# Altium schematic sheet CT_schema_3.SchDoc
size 283 x 174 mm
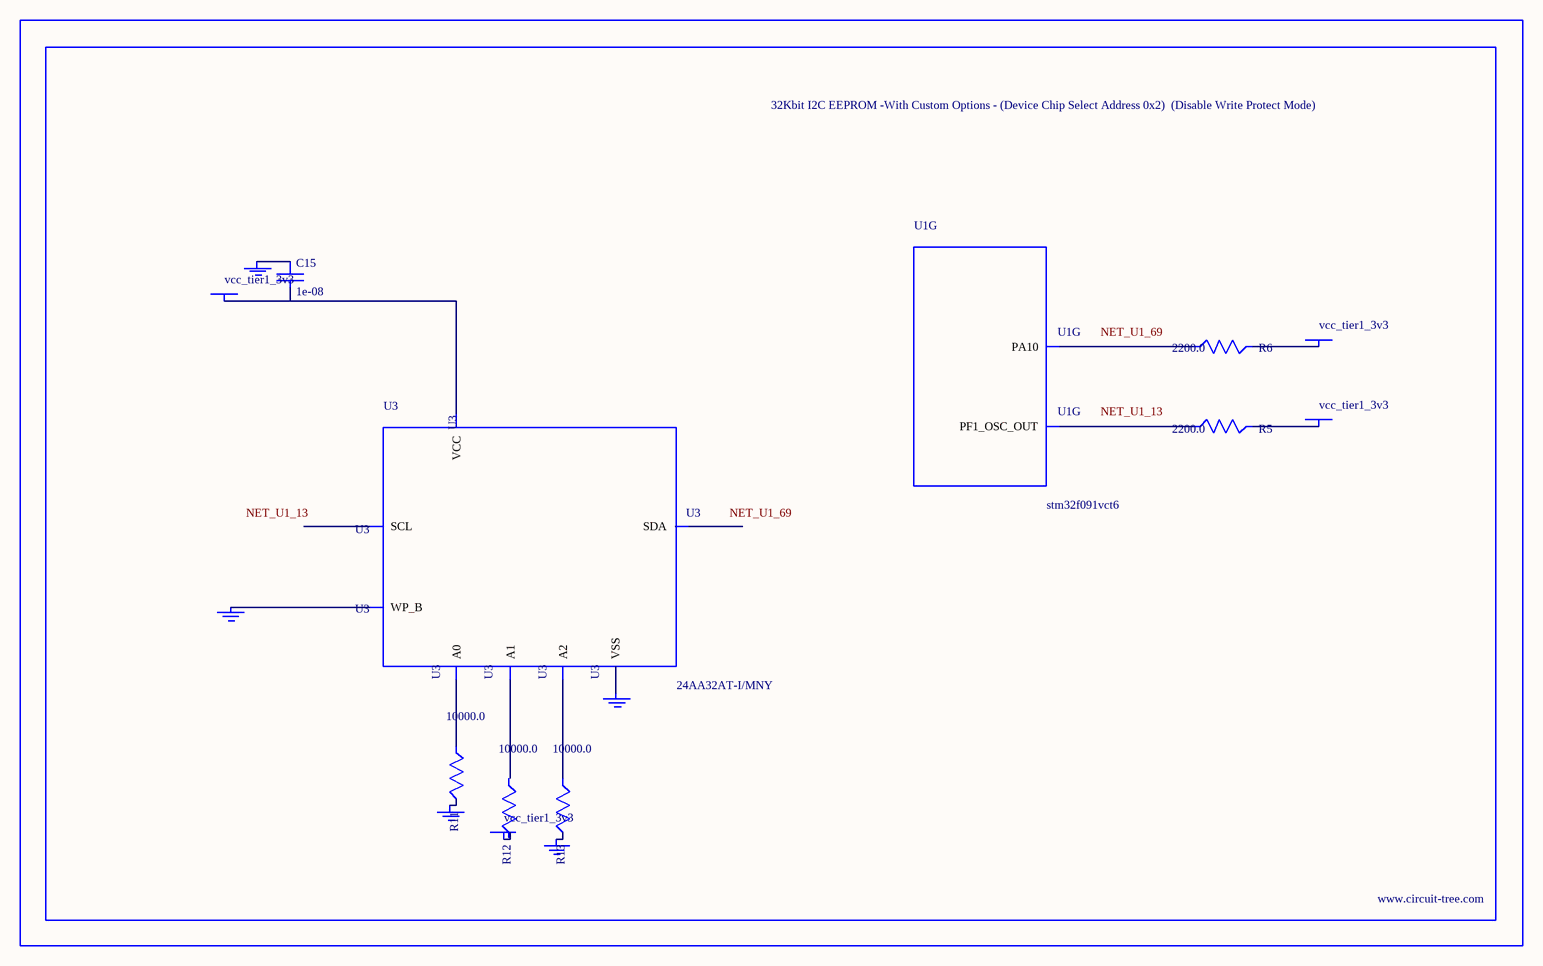
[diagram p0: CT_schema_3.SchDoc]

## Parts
BORDER2  (no value)
C15  1e-08  [C0402]
GND_INSTANCE_2_0  (no value)
GND_INSTANCE_2_1  (no value)
GND_INSTANCE_2_2  (no value)
GND_INSTANCE_2_3  (no value)
GND_INSTANCE_2_4  (no value)
POWER_INSTANCE_2_0  vcc_tier1_3v3
POWER_INSTANCE_2_1  vcc_tier1_3v3
POWER_INSTANCE_2_2  vcc_tier1_3v3
POWER_INSTANCE_2_3  vcc_tier1_3v3
R5  2200.0  [R0603]
R6  2200.0  [R0603]
R11  10000.0  [R0603]
R12  10000.0  [R0603]
R13  10000.0  [R0603]
U1  stm32f091vct6  [LQFP100]  (part G of 9)
U3  24AA32AT-I/MNY  [TDFN-8/6MM]

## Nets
NetC15_1: C15.1 GND_INSTANCE_2_3.0(GND)
NetC15_2: C15.2 POWER_INSTANCE_2_1.0(PWR) U3.8(VCC)
NetGND_INSTANCE_2_0_0: GND_INSTANCE_2_0.0(GND) R11.2
NetGND_INSTANCE_2_1_0: GND_INSTANCE_2_1.0(GND) R13.2
NetGND_INSTANCE_2_2_0: GND_INSTANCE_2_2.0(GND) U3.7(WP_B)
NetGND_INSTANCE_2_4_0: GND_INSTANCE_2_4.0(GND) U3.4(VSS)
NetPOWER_INSTANCE_2_2_0: POWER_INSTANCE_2_2.0(PWR) R5.2
NetPOWER_INSTANCE_2_3_0: POWER_INSTANCE_2_3.0(PWR) R6.2
NetR5_1: R5.1 U1.13(PF1_OSC_OUT)
NetR6_1: R6.1 U1.69(PA10)
NetR11_1: R11.1 U3.1(A0)
NetR13_1: R13.1 U3.3(A2)

Not connected (* = marked no-connect by the designer): POWER_INSTANCE_2_0 0(PWR); R12 1 2; U3 2(A1) 5(SDA) 6(SCL)

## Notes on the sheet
- Labels drawn without touching a wire or pin: NET_U1_13, NET_U1_69

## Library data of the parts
BORDER2 = BORDER_PAGE2
C15 = C0402C103K3RAC
GND_INSTANCE_2_0-GND_INSTANCE_2_4 = GND
POWER_INSTANCE_2_0-POWER_INSTANCE_2_3 = PWR
R5 R6 = RC0603JR-072K2L
R11-R13 = RC0603JR-0710KL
